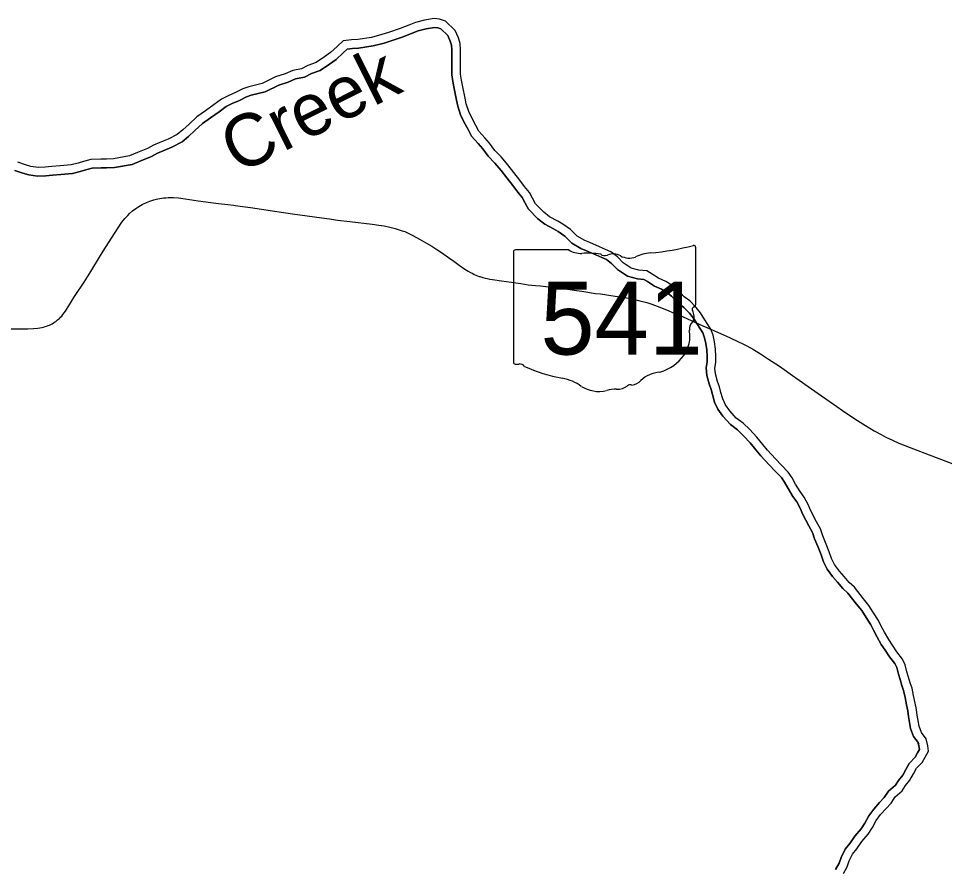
# Model space of a CAD drawing. Extents: x -12.1 to 34, y 0 to 22.
# Drawn here: x 7.88 to 9.452, y 17.456 to 18.899 of the extents above; entities that cross this region are included whole.
import ezdxf

# ---------------------------------------------------------------- set-up
doc = ezdxf.new("R2010")
doc.units = 0
for name, color, linetype in [('GM_X_County_Road', 7, 'Continuous'), ('GM_X_Major_River', 7, 'Continuous'), ('GM_X_Major_River_Text', 7, 'Continuous'), ('GM_X_State_Route', 7, 'Continuous'), ('GM_X_State_Shield', 7, 'Continuous')]:
    doc.layers.add(name, color=color, linetype=linetype)

msp = doc.modelspace()

# ---------------------------------------------------------------- linework, layer by layer
at = {"layer": 'GM_X_County_Road'}
for points in [[(8.7572, 18.4455), (8.7658, 18.4446), (8.7878, 18.4421), (8.7926, 18.4416)], [(8.7926, 18.4416), (8.8006, 18.4407), (8.8273, 18.4368)], [(8.8273, 18.4368), (8.8363, 18.4356), (8.8593, 18.4321), (8.8677, 18.431)], [(8.8677, 18.431), (8.8928, 18.4275), (8.9083, 18.4251), (8.9215, 18.4226), (8.9346, 18.4196), (8.9464, 18.4165), (8.9548, 18.4139), (8.9641, 18.4105), (8.9798, 18.4042), (8.993, 18.3986)], [(8.993, 18.3986), (9.0018, 18.3948), (9.0417, 18.377), (9.048, 18.3742), (9.0563, 18.3705), (9.0866, 18.3569), (9.1022, 18.3496), (9.1093, 18.3461)]]:
    msp.add_lwpolyline(points, dxfattribs=at)
at = {"layer": 'GM_X_Major_River'}
for points in [[(8.6561, 18.7172), (8.6493, 18.7299), (8.6442, 18.7409), (8.6398, 18.7537), (8.638, 18.7632), (8.6339, 18.7828), (8.6317, 18.7941), (8.6302, 18.8044), (8.6301, 18.8144), (8.6304, 18.8251), (8.6302, 18.846), (8.6298, 18.8563), (8.6265, 18.8656), (8.6211, 18.8783), (8.6046, 18.8942), (8.5947, 18.8977), (8.5854, 18.8987), (8.5688, 18.8957), (8.5535, 18.892), (8.5426, 18.8873), (8.5277, 18.8819), (8.5079, 18.8749), (8.4965, 18.8713), (8.4792, 18.8665), (8.4558, 18.8632), (8.4451, 18.8627), (8.4309, 18.8605), (8.4207, 18.8512), (8.4098, 18.8408), (8.3992, 18.8336), (8.3851, 18.8239), (8.3713, 18.8191), (8.3603, 18.8134), (8.3458, 18.8104), (8.3323, 18.8046), (8.316, 18.7995), (8.2934, 18.7883), (8.2707, 18.7828), (8.2608, 18.7795), (8.2485, 18.773), (8.2361, 18.7676), (8.2248, 18.7618), (8.2121, 18.7525), (8.1976, 18.7421), (8.1828, 18.732), (8.1694, 18.7194), (8.1588, 18.7098), (8.1493, 18.7019), (8.1341, 18.6936), (8.1199, 18.6881), (8.1089, 18.6834), (8.0991, 18.6777), (8.0821, 18.6711), (8.0686, 18.6653), (8.0413, 18.6605), (8.0293, 18.66), (8.0197, 18.66), (8.003, 18.6591), (7.9902, 18.6558), (7.981, 18.6533), (7.9693, 18.6503), (7.9505, 18.6484), (7.9363, 18.6476), (7.9253, 18.6465), (7.9133, 18.646), (7.9008, 18.6477), (7.8919, 18.6505), (7.8788, 18.655)], [(8.643, 18.7101), (8.6359, 18.7233), (8.6304, 18.7354), (8.6254, 18.7498), (8.6234, 18.7603), (8.6193, 18.7798), (8.617, 18.7916), (8.6153, 18.8033), (8.6152, 18.8145), (8.6155, 18.8252), (8.6153, 18.8457), (8.615, 18.8535), (8.6126, 18.8602), (8.6086, 18.8697), (8.5966, 18.8812), (8.5914, 18.8831), (8.5859, 18.8836), (8.5718, 18.8811), (8.5582, 18.8778), (8.5481, 18.8735), (8.5327, 18.8678), (8.5126, 18.8608), (8.5008, 18.857), (8.4822, 18.852), (8.4571, 18.8483), (8.4466, 18.8479), (8.4377, 18.8465), (8.4309, 18.8403), (8.4192, 18.8291), (8.4076, 18.8213), (8.3918, 18.8105), (8.3772, 18.8054), (8.3654, 18.7992), (8.3503, 18.7961), (8.3375, 18.7906), (8.3216, 18.7857), (8.2985, 18.7742), (8.2748, 18.7685), (8.2667, 18.7658), (8.2549, 18.7596), (8.2425, 18.7542), (8.2326, 18.7491), (8.2208, 18.7405), (8.2061, 18.7299), (8.1921, 18.7203), (8.1795, 18.7085), (8.1686, 18.6985), (8.1577, 18.6895), (8.1403, 18.68), (8.1255, 18.6743), (8.1157, 18.6701), (8.1055, 18.6642), (8.0877, 18.6573), (8.0729, 18.651), (8.0429, 18.6457), (8.0296, 18.6452), (8.0201, 18.6451), (8.0053, 18.6444), (7.9941, 18.6415), (7.9848, 18.6389), (7.9719, 18.6357), (7.9517, 18.6336), (7.9375, 18.6328), (7.9264, 18.6316), (7.9125, 18.6311), (7.8976, 18.6331), (7.8873, 18.6363), (7.8739, 18.6409)], [(7.8739, 18.6409), (7.8873, 18.6363), (7.8976, 18.6331), (7.9125, 18.6311), (7.9264, 18.6316), (7.9375, 18.6328), (7.9517, 18.6336), (7.9719, 18.6357), (7.9848, 18.6389), (7.9941, 18.6415), (8.0053, 18.6444), (8.0201, 18.6451), (8.0296, 18.6452), (8.0429, 18.6457), (8.0729, 18.651), (8.0877, 18.6573), (8.1055, 18.6642), (8.1157, 18.6701), (8.1255, 18.6743), (8.1403, 18.68), (8.1577, 18.6895), (8.1686, 18.6985), (8.1795, 18.7085), (8.1921, 18.7203), (8.2061, 18.7299), (8.2208, 18.7405), (8.2326, 18.7491), (8.2425, 18.7542), (8.2549, 18.7596), (8.2667, 18.7658), (8.2748, 18.7685), (8.2985, 18.7742), (8.3216, 18.7857), (8.3375, 18.7906), (8.3503, 18.7961), (8.3654, 18.7992), (8.3772, 18.8054), (8.3918, 18.8105), (8.4076, 18.8213), (8.4192, 18.8291), (8.4309, 18.8403), (8.4377, 18.8465), (8.4466, 18.8479), (8.4571, 18.8483), (8.4822, 18.852), (8.5008, 18.857), (8.5126, 18.8608), (8.5327, 18.8678), (8.5481, 18.8735), (8.5582, 18.8778), (8.5718, 18.8811), (8.5859, 18.8836), (8.5914, 18.8831), (8.5966, 18.8812), (8.6086, 18.8697), (8.6126, 18.8602), (8.615, 18.8535), (8.6153, 18.8457), (8.6155, 18.8252), (8.6152, 18.8145), (8.6153, 18.8033), (8.617, 18.7916), (8.6193, 18.7798), (8.6234, 18.7603), (8.6254, 18.7498), (8.6304, 18.7354), (8.6359, 18.7233), (8.643, 18.7102)], [(9.4204, 17.6758), (9.4125, 17.6867), (9.4085, 17.6974), (9.4051, 17.7158), (9.404, 17.7254), (9.4018, 17.7364), (9.3992, 17.7492), (9.3966, 17.7616), (9.3933, 17.7709), (9.3904, 17.7804), (9.3879, 17.7897), (9.3846, 17.8017), (9.3802, 17.8113), (9.3705, 17.8237), (9.3633, 17.8346), (9.3569, 17.8442), (9.3497, 17.8566), (9.3443, 17.8668), (9.3396, 17.8764), (9.3313, 17.8898), (9.323, 17.9022), (9.3141, 17.9135), (9.2986, 17.9333), (9.2897, 17.9414), (9.2811, 17.9513), (9.2732, 17.9605), (9.265, 17.9718), (9.2599, 17.9821), (9.2559, 17.993), (9.2508, 18.0065), (9.245, 18.0207), (9.241, 18.0324), (9.2342, 18.0444), (9.2248, 18.0628), (9.2201, 18.0738), (9.2136, 18.0859), (9.2068, 18.0954), (9.1989, 18.1081), (9.1928, 18.1191), (9.1863, 18.1287), (9.1749, 18.1403), (9.1648, 18.1509), (9.1509, 18.1657), (9.143, 18.1756), (9.1329, 18.188), (9.1211, 18.2007), (9.1097, 18.2116), (9.0982, 18.2204), (9.0871, 18.2328), (9.0799, 18.243), (9.0752, 18.2529), (9.072, 18.2639), (9.0698, 18.2732), (9.0665, 18.2827), (9.0628, 18.2955), (9.062, 18.3051), (9.0637, 18.3144), (9.0637, 18.3254), (9.0632, 18.3375), (9.0613, 18.3495), (9.0588, 18.3609), (9.0548, 18.3715), (9.0451, 18.3871), (9.0375, 18.3988), (9.03, 18.4083), (9.0192, 18.4193), (9.0099, 18.4263), (8.9985, 18.4386), (8.9888, 18.4457), (8.9785, 18.4523), (8.9664, 18.4576), (8.9553, 18.4646), (8.9464, 18.4702), (8.9329, 18.4715), (8.9197, 18.475), (8.9062, 18.4841), (8.8965, 18.494), (8.8854, 18.5024), (8.8762, 18.5063), (8.8662, 18.5112), (8.8498, 18.5182), (8.8409, 18.5216), (8.8284, 18.529), (8.8166, 18.5406), (8.8041, 18.5494), (8.7952, 18.5547), (8.7813, 18.5621), (8.7716, 18.5698), (8.7577, 18.5839), (8.7526, 18.5935), (8.7472, 18.6034), (8.739, 18.6133), (8.7307, 18.6242), (8.7207, 18.6373), (8.7106, 18.65), (8.6995, 18.6631), (8.6884, 18.6748), (8.6794, 18.6868), (8.6712, 18.6963), (8.6612, 18.7076), (8.6561, 18.7172)], [(9.4083, 17.6671), (9.3992, 17.6796), (9.3941, 17.6934), (9.3904, 17.7136), (9.3893, 17.7231), (9.3872, 17.7335), (9.3846, 17.7462), (9.3822, 17.7576), (9.3792, 17.7662), (9.3761, 17.7763), (9.3735, 17.7857), (9.3705, 17.7967), (9.3674, 17.8035), (9.3584, 17.815), (9.351, 17.8264), (9.3443, 17.8362), (9.3367, 17.8493), (9.331, 17.8601), (9.3265, 17.8692), (9.3188, 17.8818), (9.311, 17.8934), (9.3024, 17.9043), (9.2877, 17.9231), (9.2791, 17.931), (9.2698, 17.9416), (9.2615, 17.9512), (9.2522, 17.9641), (9.2462, 17.9762), (9.242, 17.9879), (9.237, 18.0011), (9.2311, 18.0155), (9.2274, 18.0263), (9.2211, 18.0374), (9.2113, 18.0565), (9.2067, 18.0674), (9.201, 18.078), (9.1944, 18.0871), (9.1861, 18.1006), (9.1801, 18.1113), (9.1747, 18.1192), (9.1641, 18.13), (9.154, 18.1407), (9.1396, 18.156), (9.1314, 18.1663), (9.1217, 18.1782), (9.1105, 18.1902), (9.1, 18.2003), (9.0881, 18.2094), (9.0755, 18.2235), (9.067, 18.2355), (9.0613, 18.2476), (9.0576, 18.2601), (9.0554, 18.269), (9.0523, 18.2783), (9.0481, 18.2928), (9.0471, 18.3058), (9.0489, 18.3156), (9.0488, 18.325), (9.0484, 18.336), (9.0467, 18.3467), (9.0445, 18.3566), (9.0413, 18.3649), (9.0325, 18.3791), (9.0254, 18.3901), (9.0188, 18.3985), (9.0094, 18.4081), (8.9999, 18.4152), (8.9885, 18.4275), (8.9804, 18.4334), (8.9715, 18.4392), (8.9594, 18.4444), (8.9474, 18.452), (8.9414, 18.4558), (8.9303, 18.4568), (8.9135, 18.4612), (8.8966, 18.4726), (8.8866, 18.4828), (8.8779, 18.4894), (8.87, 18.4927), (8.86, 18.4976), (8.8442, 18.5044), (8.8344, 18.5082), (8.8193, 18.5171), (8.807, 18.5292), (8.796, 18.5369), (8.7879, 18.5417), (8.7731, 18.5496), (8.7616, 18.5587), (8.7455, 18.575), (8.7395, 18.5864), (8.7348, 18.595), (8.7273, 18.604), (8.7189, 18.6152), (8.7089, 18.6282), (8.6991, 18.6406), (8.6884, 18.6531), (8.677, 18.6651), (8.6678, 18.6774), (8.66, 18.6865), (8.6488, 18.6991), (8.643, 18.7102)], [(8.643, 18.7102), (8.6488, 18.6991), (8.66, 18.6865), (8.6678, 18.6774), (8.677, 18.6651), (8.6884, 18.6531), (8.6991, 18.6406), (8.7089, 18.6282), (8.7189, 18.6152), (8.7273, 18.604), (8.7348, 18.595), (8.7395, 18.5864), (8.7455, 18.575), (8.7616, 18.5587), (8.7731, 18.5496), (8.7879, 18.5417), (8.796, 18.5369), (8.807, 18.5292), (8.8193, 18.5171), (8.8344, 18.5082), (8.8442, 18.5044), (8.86, 18.4976), (8.87, 18.4927), (8.8779, 18.4894), (8.8866, 18.4828), (8.8966, 18.4726), (8.9135, 18.4612), (8.9303, 18.4568), (8.9414, 18.4558), (8.9474, 18.452), (8.9594, 18.4444), (8.9715, 18.4392), (8.9804, 18.4334), (8.9885, 18.4275), (8.9999, 18.4152), (9.0094, 18.4081), (9.0188, 18.3985), (9.0254, 18.3901), (9.0325, 18.3791), (9.0413, 18.3649), (9.0445, 18.3566), (9.0467, 18.3467), (9.0484, 18.336), (9.0488, 18.325), (9.0489, 18.3156), (9.0471, 18.3058), (9.0481, 18.2928), (9.0523, 18.2783), (9.0554, 18.269), (9.0576, 18.2601), (9.0613, 18.2476), (9.067, 18.2355), (9.0755, 18.2235), (9.0881, 18.2094), (9.1, 18.2003), (9.1105, 18.1902), (9.1217, 18.1782), (9.1314, 18.1663), (9.1396, 18.156), (9.154, 18.1407), (9.1641, 18.13), (9.1747, 18.1192), (9.1801, 18.1113), (9.1861, 18.1006), (9.1944, 18.0871), (9.201, 18.078), (9.2067, 18.0674), (9.2113, 18.0565), (9.2211, 18.0374), (9.2274, 18.0263), (9.2311, 18.0155), (9.237, 18.0011), (9.242, 17.9879), (9.2462, 17.9762), (9.2522, 17.9641), (9.2615, 17.9512), (9.2698, 17.9416), (9.2791, 17.931), (9.2877, 17.9231), (9.3024, 17.9043), (9.311, 17.8934), (9.3188, 17.8818), (9.3265, 17.8692), (9.331, 17.8601), (9.3367, 17.8493), (9.3443, 17.8362), (9.351, 17.8264), (9.3584, 17.815), (9.3674, 17.8035), (9.3705, 17.7967), (9.3735, 17.7857), (9.3761, 17.7763), (9.3792, 17.7662), (9.3822, 17.7576), (9.3846, 17.7462), (9.3872, 17.7335), (9.3893, 17.7231), (9.3904, 17.7136), (9.3941, 17.6934), (9.3992, 17.6796), (9.4066, 17.6694)], [(9.3915, 17.6339), (9.3919, 17.6347), (9.4017, 17.6446), (9.4059, 17.6518), (9.4091, 17.6577), (9.4086, 17.661), (9.4059, 17.6723)], [(9.4066, 17.6694), (9.4086, 17.661), (9.4091, 17.6577), (9.4059, 17.6518), (9.4017, 17.6446), (9.3919, 17.6347), (9.3915, 17.6339)], [(9.412, 17.6339), (9.4136, 17.6355), (9.4188, 17.6445), (9.4244, 17.6548), (9.4233, 17.6637), (9.4204, 17.6758)], [(9.2668, 17.4541), (9.2726, 17.4647), (9.2763, 17.4742), (9.2829, 17.4882), (9.2911, 17.4981), (9.2995, 17.5103), (9.3102, 17.523), (9.3164, 17.5328), (9.3229, 17.545), (9.3314, 17.5564), (9.3415, 17.5679), (9.3492, 17.5761), (9.3566, 17.587), (9.3682, 17.5974), (9.3735, 17.6053), (9.3806, 17.6143), (9.3862, 17.6238), (9.3915, 17.6339)], [(9.3915, 17.6339), (9.3862, 17.6238), (9.3806, 17.6143), (9.3735, 17.6053), (9.3682, 17.5974), (9.3566, 17.587), (9.3492, 17.5761), (9.3415, 17.5679), (9.3314, 17.5564), (9.3229, 17.545), (9.3164, 17.5328), (9.3102, 17.523), (9.2995, 17.5103), (9.2911, 17.4981), (9.2829, 17.4882), (9.2763, 17.4742), (9.2726, 17.4647), (9.2668, 17.4541)], [(9.2799, 17.447), (9.2861, 17.4584), (9.29, 17.4684), (9.2956, 17.4802), (9.3029, 17.4891), (9.3114, 17.5013), (9.3223, 17.5142), (9.3293, 17.5253), (9.3356, 17.5371), (9.3429, 17.5471), (9.3524, 17.5578), (9.3609, 17.5668), (9.3679, 17.5772), (9.3795, 17.5876), (9.3855, 17.5965), (9.3929, 17.6058), (9.3992, 17.6166), (9.4041, 17.6258), (9.412, 17.6339)]]:
    msp.add_lwpolyline(points, dxfattribs=at)
at = {"layer": 'GM_X_State_Route'}
for points in [[(7.8636, 18.372), (7.8817, 18.3717), (7.8956, 18.3718), (7.9054, 18.3722), (7.9129, 18.3728), (7.9163, 18.3734), (7.9197, 18.3741), (7.9226, 18.3748), (7.9252, 18.3756), (7.9275, 18.3763), (7.9301, 18.3773), (7.9324, 18.3783), (7.9348, 18.3794), (7.937, 18.3805), (7.9393, 18.3819), (7.9412, 18.383), (7.9432, 18.3844), (7.9463, 18.3869), (7.9494, 18.3895), (7.9514, 18.3915), (7.9533, 18.3936), (7.9555, 18.3961), (7.9577, 18.399), (7.9597, 18.4018), (7.9617, 18.4047), (7.9673, 18.4135), (7.9742, 18.4249), (7.9764, 18.4282), (7.9913, 18.4513), (8.0025, 18.4691), (8.0173, 18.4934), (8.0239, 18.5038), (8.0381, 18.5258), (8.0494, 18.5435), (8.0556, 18.5527), (8.0606, 18.5592), (8.0653, 18.5645), (8.0686, 18.5678), (8.0734, 18.5721), (8.079, 18.5763), (8.0845, 18.5798), (8.0901, 18.583), (8.097, 18.5862), (8.1031, 18.5886), (8.1098, 18.5907), (8.1166, 18.5924), (8.1196, 18.593), (8.123, 18.5935), (8.1263, 18.594), (8.13, 18.5944), (8.1338, 18.5946), (8.1376, 18.5947), (8.1429, 18.5946), (8.1517, 18.594), (8.1627, 18.5926), (8.1851, 18.589), (8.2065, 18.5861), (8.2192, 18.5846), (8.2353, 18.5828), (8.2451, 18.5816), (8.248, 18.5813), (8.2739, 18.5776), (8.2924, 18.5749), (8.3183, 18.571), (8.3448, 18.5673), (8.3661, 18.5641), (8.3863, 18.5613), (8.4076, 18.5584), (8.4214, 18.5565), (8.4422, 18.554), (8.4804, 18.5496), (8.4914, 18.548), (8.5006, 18.5465), (8.5104, 18.5446), (8.5194, 18.5422), (8.5277, 18.5396), (8.5314, 18.5383), (8.5354, 18.5368), (8.5388, 18.5354)], [(8.5388, 18.5354), (8.5424, 18.5338), (8.5457, 18.5322), (8.5492, 18.5304), (8.5605, 18.5241), (8.5685, 18.5197)], [(8.5685, 18.5197), (8.5726, 18.5175), (8.5816, 18.5121), (8.5899, 18.5068), (8.5981, 18.5013), (8.6095, 18.4932), (8.6188, 18.4866)], [(8.6188, 18.4866), (8.628, 18.48), (8.6375, 18.4734), (8.6434, 18.4697), (8.6471, 18.4676), (8.651, 18.4656), (8.6535, 18.4643), (8.6563, 18.4631), (8.6588, 18.462), (8.6617, 18.4609), (8.6632, 18.4605)], [(8.6632, 18.4605), (8.6647, 18.46), (8.6682, 18.459), (8.6718, 18.4581), (8.6755, 18.4572), (8.6799, 18.4563), (8.6846, 18.4555), (8.6995, 18.4532), (8.7168, 18.451), (8.7202, 18.4504), (8.7324, 18.4486), (8.745, 18.4468), (8.7572, 18.4455)], [(8.7572, 18.4455), (8.7658, 18.4446), (8.7878, 18.4421), (8.7926, 18.4416)], [(8.7926, 18.4416), (8.8006, 18.4407), (8.8273, 18.4368)], [(8.8273, 18.4368), (8.8363, 18.4356), (8.8593, 18.4321), (8.8677, 18.431)], [(8.8677, 18.431), (8.8928, 18.4275), (8.9083, 18.4251), (8.9215, 18.4226), (8.9346, 18.4196), (8.9464, 18.4165), (8.9548, 18.4139), (8.9641, 18.4105), (8.9798, 18.4042), (8.993, 18.3986)], [(8.993, 18.3986), (9.0018, 18.3948), (9.0417, 18.377), (9.048, 18.3742), (9.0563, 18.3705), (9.0866, 18.3569), (9.1022, 18.3496), (9.1093, 18.3461)], [(9.1093, 18.3461), (9.1161, 18.3427), (9.1273, 18.3365), (9.1394, 18.3293), (9.1531, 18.3205), (9.1715, 18.3082), (9.1977, 18.2899)], [(9.1977, 18.2899), (9.1992, 18.2888), (9.2259, 18.2701), (9.243, 18.258), (9.2631, 18.244), (9.2842, 18.2295), (9.304, 18.2163), (9.3177, 18.2075), (9.3322, 18.1988), (9.3438, 18.1923), (9.3521, 18.188), (9.3631, 18.1828), (9.3743, 18.178), (9.3992, 18.1682), (9.4253, 18.1581), (9.4584, 18.1452), (9.5003, 18.1292)]]:
    msp.add_lwpolyline(points, dxfattribs=at)
at = {"layer": 'GM_X_State_Shield'}
for p, q in [((8.7203, 18.5026), (8.7203, 18.315)), ((8.8138, 18.5058), (8.7233, 18.5058)), ((9.0293, 18.4123), (9.0293, 18.5105)), ((9.0292, 18.4124), (9.0293, 18.4123))]:
    msp.add_line(p, q, dxfattribs=at)
for centre, major_axis, start_param, end_param in [((8.9192, 18.7616), (0.3277, 0), 4.814394, 5.042369), ((9.0258, 18.5109), (0.00344, 0), 6.141152, 7.989035), ((8.7238, 18.503), (0.00358, 0), 1.712693, 3.28349), ((8.8353, 18.5276), (0.0347, 0), 4.042523, 4.731795), ((8.8469, 18.4005), (0.1246, 0), 1.404758, 1.657858), ((8.8752, 18.504), (0.01, 0), 3.836095, 5.185415), ((8.8899, 18.4823), (0.0208, 0), 0.950623, 2.079405), ((8.961, 18.4485), (0.0659, 0), 1.699011, 2.107814), ((8.9167, 18.512), (0.0251, 0), 4.081561, 5.145723), ((9.0285, 18.4051), (0.00532, 0), 1.883978, 3.671073), ((8.9946, 18.3927), (0.032, 0), 5.934695, 6.695948), ((9.0256, 18.412), (0.00368, 0), 5.05454, 6.418171), ((9.0416, 18.3713), (0.0232, 0), 2.387724, 3.262537), ((8.9375, 18.3588), (0.082, 0), 5.101752, 6.440018), ((8.7238, 18.3146), (0.00361, 0), 3.00124, 4.508301), ((8.7244, 18.3338), (0.0276, 0), 4.665946, 4.897461), ((8.73, 18.3042), (0.00994, 0), 0.519207, 1.627899), ((8.8555, 18.4727), (0.2366, 0), 4.195997, 4.488961), ((8.9721, 18.2623), (0.0449, 0), 1.647645, 2.488434), ((8.7849, 18.2307), (0.074, 0), 0.823519, 1.323587), ((8.9182, 18.271), (0.00705, 0), 1.147584, 2.315152), ((8.9152, 18.2968), (0.0265, 0), 4.937069, 5.64225), ((8.865, 18.3032), (0.047, 0), 4.026481, 4.996735), ((8.8922, 18.2384), (0.0386, 0), 1.495662, 1.94098), ((8.8956, 18.2892), (0.025, 0), 4.691044, 5.507374)]:
    msp.add_ellipse(centre, major_axis=major_axis, ratio=0.8, start_param=start_param, end_param=end_param, dxfattribs=at)

# ---------------------------------------------------------------- texts
at = {"layer": 'GM_X_Major_River_Text'}
msp.add_text('Creek', height=0.08877, rotation=26.6433, dxfattribs=at).set_placement((8.2523, 18.6334))
at = {"layer": 'GM_X_State_Shield'}
msp.add_text('541', height=0.1236, dxfattribs=at).set_placement((8.7658, 18.3282))

doc.saveas('drawing.dxf')
